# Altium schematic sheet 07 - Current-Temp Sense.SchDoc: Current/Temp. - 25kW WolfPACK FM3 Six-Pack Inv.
size 431 x 279 mm; Date: 09/2024; DocumentNumber: CRD25DA12N-FMC; Revision: 2.0; SheetNumber: 7; SheetTotal: 9; SheetSize: B
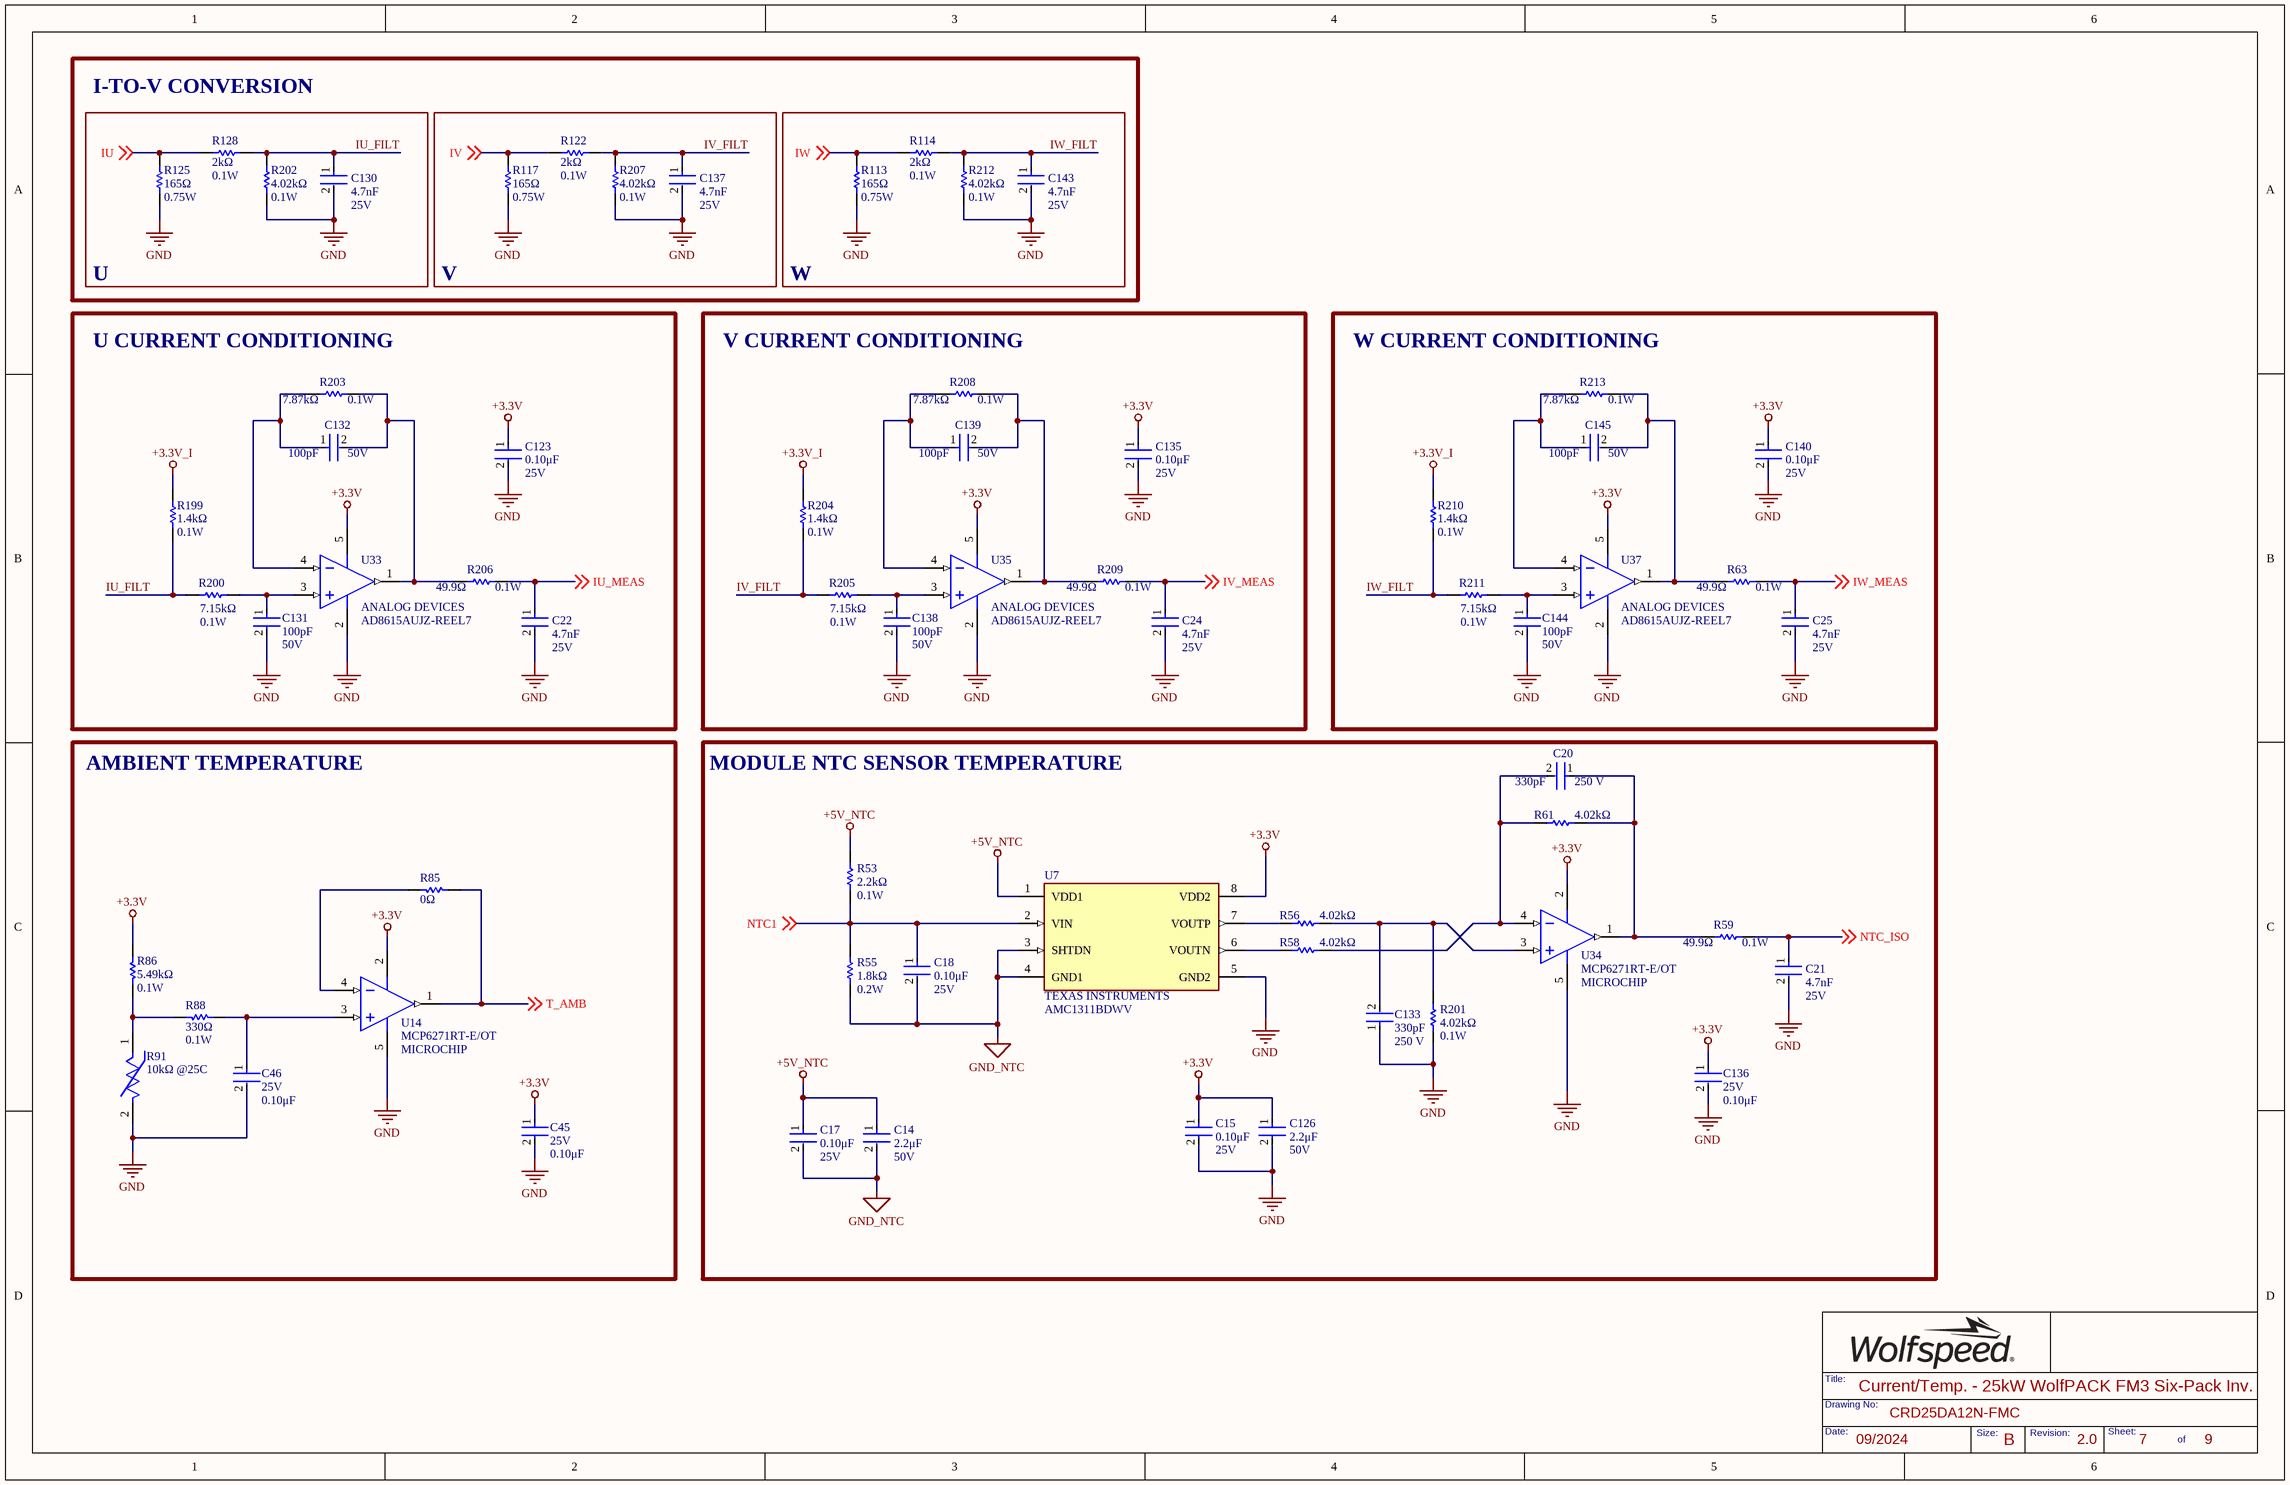
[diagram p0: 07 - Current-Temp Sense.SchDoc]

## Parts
C14  Voltage Rating: 50V  Capacitance: 2.2μF  [FP-C0603C-CF-IPC_B]  (hidden comment: GRT188R61H225ME13D)
C15  Voltage Rating: 25V  Capacitance: 0.10μF  [FP-C0603C-CF-IPC_B]  (hidden comment: C0603C104K3RACTU)
C17  Voltage Rating: 25V  Capacitance: 0.10μF  [FP-C0603C-CF-IPC_B]  (hidden comment: C0603C104K3RACTU)
C18  Voltage Rating: 25V  Capacitance: 0.10μF  [FP-C0603C-CF-IPC_B]  (hidden comment: C0603C104K3RACTU)
C20  value 330pF  Voltage Rating: 250 V  [FP-C0603C-CF-IPC_B]  (hidden comment: C0603C331JAGAC7867)
C21  Voltage Rating: 25V  Capacitance: 4.7nF  [FP-C0603C-CF-IPC_B]  (hidden comment: C0603C472K3RAC7867)
C22  Voltage Rating: 25V  Capacitance: 4.7nF  [FP-C0603C-CF-IPC_B]  (hidden comment: C0603C472K3RAC7867)
C24  Voltage Rating: 25V  Capacitance: 4.7nF  [FP-C0603C-CF-IPC_B]  (hidden comment: C0603C472K3RAC7867)
C25  Voltage Rating: 25V  Capacitance: 4.7nF  [FP-C0603C-CF-IPC_B]  (hidden comment: C0603C472K3RAC7867)
C45  Voltage Rating: 25V  Capacitance: 0.10μF  [FP-C0603C-CF-IPC_B]  (hidden comment: C0603C104K3RACTU)
C46  Voltage Rating: 25V  Capacitance: 0.10μF  [FP-C0603C-CF-IPC_B]  (hidden comment: C0603C104K3RACTU)
C123  Voltage Rating: 25V  Capacitance: 0.10μF  [FP-C0603C-CF-IPC_B]  (hidden comment: C0603C104K3RACTU)
C126  Voltage Rating: 50V  Capacitance: 2.2μF  [FP-C0603C-CF-IPC_B]  (hidden comment: GRT188R61H225ME13D)
C130  Voltage Rating: 25V  Capacitance: 4.7nF  [FP-C0603C-CF-IPC_B]  (hidden comment: C0603C472K3RAC7867)
C131  Capacitance: 100pF  Voltage: 50V  [FP-C0603C-CF-IPC_B]  (hidden comment: CL10C101JB8NNNC)
C132  Capacitance: 100pF  Voltage: 50V  [FP-C0603C-CF-IPC_B]  (hidden comment: CL10C101JB8NNNC)
C133  value 330pF  Voltage Rating: 250 V  [FP-C0603C-CF-IPC_B]  (hidden comment: C0603C331JAGAC7867)
C135  Voltage Rating: 25V  Capacitance: 0.10μF  [FP-C0603C-CF-IPC_B]  (hidden comment: C0603C104K3RACTU)
C136  Voltage Rating: 25V  Capacitance: 0.10μF  [FP-C0603C-CF-IPC_B]  (hidden comment: C0603C104K3RACTU)
C137  Voltage Rating: 25V  Capacitance: 4.7nF  [FP-C0603C-CF-IPC_B]  (hidden comment: C0603C472K3RAC7867)
C138  Capacitance: 100pF  Voltage: 50V  [FP-C0603C-CF-IPC_B]  (hidden comment: CL10C101JB8NNNC)
C139  Capacitance: 100pF  Voltage: 50V  [FP-C0603C-CF-IPC_B]  (hidden comment: CL10C101JB8NNNC)
C140  Voltage Rating: 25V  Capacitance: 0.10μF  [FP-C0603C-CF-IPC_B]  (hidden comment: C0603C104K3RACTU)
C143  Voltage Rating: 25V  Capacitance: 4.7nF  [FP-C0603C-CF-IPC_B]  (hidden comment: C0603C472K3RAC7867)
C144  Capacitance: 100pF  Voltage: 50V  [FP-C0603C-CF-IPC_B]  (hidden comment: CL10C101JB8NNNC)
C145  Capacitance: 100pF  Voltage: 50V  [FP-C0603C-CF-IPC_B]  (hidden comment: CL10C101JB8NNNC)
R53  value 2.2kΩ  Power: 0.1W  [FP-MCR03-IPC_B]  (hidden comment: RC0603FR-072K2L)
R55  Resistance: 1.8kΩ  Max Power Dissipation: 0.2W  [FP-MCR03-IPC_B]  (hidden comment: ERJ-PB3B1801V)
R56  Resistance: 4.02kΩ  [FP-MCR03-IPC_B]  (hidden comment: ERA3AEB4021V)
R58  Resistance: 4.02kΩ  [FP-MCR03-IPC_B]  (hidden comment: ERA3AEB4021V)
R59  Resistance: 49.9Ω  Power Rating: 0.1W  [FP-MCR03-IPC_B]  (hidden comment: ERJ-3EKF49R9V)
R61  Resistance: 4.02kΩ  [FP-MCR03-IPC_B]  (hidden comment: ERA3AEB4021V)
R63  Resistance: 49.9Ω  Power Rating: 0.1W  [FP-MCR03-IPC_B]  (hidden comment: ERJ-3EKF49R9V)
R85  Resistance: 0Ω  [FP-MCR03-IPC_B]  (hidden comment: CRCW06030000Z0EB)
R86  value 5.49kΩ  Power Rating: 0.1W  [FP-MCR03-IPC_B]  (hidden comment: RC0603FR-075K49L)
R88  Resistance: 330Ω  Power Rating: 0.1W  [FP-MCR03-IPC_B]  (hidden comment: RC0603FR-13330RL)
R91  value 10kΩ @25C  [FP-NCU18-0_15-IPC_B]  (hidden comment: NCU18XH103F6SRB)
R113  value 165Ω  Power: 0.75W  [FP-CRCW2010-e3-IPC_B]  (hidden comment: CRCW2010165RFKEF)
R114  Resistance: 2kΩ  Power Rating: 0.1W  [FP-MCR03-IPC_B]  (hidden comment: RT0603DRE072KL)
R117  value 165Ω  Power: 0.75W  [FP-CRCW2010-e3-IPC_B]  (hidden comment: CRCW2010165RFKEF)
R122  Resistance: 2kΩ  Power Rating: 0.1W  [FP-MCR03-IPC_B]  (hidden comment: RT0603DRE072KL)
R125  value 165Ω  Power: 0.75W  [FP-CRCW2010-e3-IPC_B]  (hidden comment: CRCW2010165RFKEF)
R128  Resistance: 2kΩ  Power Rating: 0.1W  [FP-MCR03-IPC_B]  (hidden comment: RT0603DRE072KL)
R199  value 1.4kΩ  Power: 0.1W  [FP-MCR03-IPC_B]  (hidden comment: RT0603DRD071K4L)
R200  Resistance: 7.15kΩ  Power Rating: 0.1W  [FP-MCR03-IPC_B]  (hidden comment: RMCF0603FT7K15)
R201  Power: 0.1W  Resistance: 4.02kΩ  [FP-MCR03-IPC_B]  (hidden comment: ERA3AEB4021V)
R202  Resistance: 4.02kΩ  Power Rating: 0.1W  [FP-MCR03-IPC_B]  (hidden comment: ERA3AEB4021V)
R203  Resistance: 7.87kΩ  Max Power Dissipation: 0.1W  [FP-MCR03-IPC_B]  (hidden comment: RC0603FR-077K87L)
R204  value 1.4kΩ  Power: 0.1W  [FP-MCR03-IPC_B]  (hidden comment: RT0603DRD071K4L)
R205  Resistance: 7.15kΩ  Power Rating: 0.1W  [FP-MCR03-IPC_B]  (hidden comment: RMCF0603FT7K15)
R206  Resistance: 49.9Ω  Power Rating: 0.1W  [FP-MCR03-IPC_B]  (hidden comment: ERJ-3EKF49R9V)
R207  Resistance: 4.02kΩ  Power Rating: 0.1W  [FP-MCR03-IPC_B]  (hidden comment: ERA3AEB4021V)
R208  Resistance: 7.87kΩ  Max Power Dissipation: 0.1W  [FP-MCR03-IPC_B]  (hidden comment: RC0603FR-077K87L)
R209  Resistance: 49.9Ω  Power Rating: 0.1W  [FP-MCR03-IPC_B]  (hidden comment: ERJ-3EKF49R9V)
R210  value 1.4kΩ  Power: 0.1W  [FP-MCR03-IPC_B]  (hidden comment: RT0603DRD071K4L)
R211  Resistance: 7.15kΩ  Power Rating: 0.1W  [FP-MCR03-IPC_B]  (hidden comment: RMCF0603FT7K15)
R212  Resistance: 4.02kΩ  Power Rating: 0.1W  [FP-MCR03-IPC_B]  (hidden comment: ERA3AEB4021V)
R213  Resistance: 7.87kΩ  Max Power Dissipation: 0.1W  [FP-MCR03-IPC_B]  (hidden comment: RC0603FR-077K87L)
U7  AMC1311BDWV  Manufacturer: TEXAS INSTRUMENTS  [FP-DWV0008A-MFG]
U14  Manufacturer: MICROCHIP  [ADI-UJ-5_M]  (hidden comment: MCP6271RT-E/OT)
U33  Manufacturer: ANALOG DEVICES  [ADI-UJ-5_M]  (hidden comment: AD8615AUJZ-REEL7)
U34  Manufacturer: MICROCHIP  [ADI-UJ-5_M]  (hidden comment: MCP6271RT-E/OT)
U35  Manufacturer: ANALOG DEVICES  [ADI-UJ-5_M]  (hidden comment: AD8615AUJZ-REEL7)
U37  Manufacturer: ANALOG DEVICES  [ADI-UJ-5_M]  (hidden comment: AD8615AUJZ-REEL7)

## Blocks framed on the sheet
V: C137 R117 R122 R207
W: C143 R113 R114 R212
U CURRENT CONDITIONING: C22 C123 C131 C132 R199 R200 R203 R206 U33
V CURRENT CONDITIONING: C24 C135 C138 C139 R204 R205 R208 R209 U35
W CURRENT CONDITIONING: C25 C140 C144 C145 R63 R210 R211 R213 U37
AMBIENT TEMPERATURE: C45 C46 R85 R86 R88 R91 U14
MODULE NTC SENSOR TEMPERATURE: C14 C15 C17 C18 C20 C21 C126 C133 C136 R53 R55 R56 R58 R59 R61 R201 U7 U34

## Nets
+3.3V: C15.1 C45.1 C123.1 C126.1 C135.1 C136.1 C140.1 R86.2 U7.8(VDD2) U14.2(+V) U33.5(+V) U34.2(+V) U35.5(+V) U37.5(+V)
+3.3V_I: R199.2 R204.2 R210.2
+5V_NTC: C14.1 C17.1 R53.2 U7.1(VDD1)
GND: C15.2 C21.2 C22.2 C24.2 C25.2 C45.2 C46.2 C123.2 C126.2 C130.2 C131.2 C133.1 C135.2 C136.2 C137.2 C138.2 C140.2 C143.2 C144.2 R91.2 R113.1 R117.1 R125.1 R201.2 R202.1 R207.1 R212.1 U7.5(GND2) U14.5(-V) U33.2(-V) U34.5(-V) U35.2(-V) U37.2(-V)
GND_NTC: C14.2 C17.2 C18.2 R55.1 U7.3(SHTDN) U7.4(GND1)
IU: R125.2 R128.1 ; off-sheet IU
IU_FILT: C130.1 R128.2 R199.1 R200.1 R202.2
IU_MEAS: C22.1 R206.2 ; off-sheet IU_MEAS
IV: R117.2 R122.1 ; off-sheet IV
IV_FILT: C137.1 R122.2 R204.1 R205.1 R207.2
IV_MEAS: C24.1 R209.2 ; off-sheet IV_MEAS
IW: R113.2 R114.1 ; off-sheet IW
IW_FILT: C143.1 R114.2 R210.1 R211.1 R212.2
IW_MEAS: C25.1 R63.2 ; off-sheet IW_MEAS
NTC1: C18.1 R53.1 R55.2 U7.2(VIN) ; off-sheet NTC1
NTC_ISO: C21.1 R59.2 ; off-sheet NTC_ISO
T_AMB: R85.1 U14.1(OUT) ; off-sheet T_AMB
NetC20_1: C20.1 R59.1 R61.1 U34.1(OUT)
NetC20_2: C20.2 R58.1 R61.2 U34.4(-IN)
NetC46_1: C46.1 R88.2 U14.3(+IN)
NetC131_1: C131.1 R200.2 U33.3(+IN)
NetC132_1: C132.1 R203.1 U33.4(-IN)
NetC132_2: C132.2 R203.2 R206.1 U33.1(OUT)
NetC133_2: C133.2 R56.1 R201.1 U34.3(+IN)
NetC138_1: C138.1 R205.2 U35.3(+IN)
NetC139_1: C139.1 R208.1 U35.4(-IN)
NetC139_2: C139.2 R208.2 R209.1 U35.1(OUT)
NetC144_1: C144.1 R211.2 U37.3(+IN)
NetC145_1: C145.1 R213.1 U37.4(-IN)
NetC145_2: C145.2 R63.1 R213.2 U37.1(OUT)
NetR56_2: R56.2 U7.7(VOUTP)
NetR58_2: R58.2 U7.6(VOUTN)
NetR85_2: R85.2 U14.4(-IN)
NetR86_1: R86.1 R88.1 R91.1

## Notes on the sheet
- I-TO-V CONVERSION
- U

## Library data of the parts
C14 C126 = GRT188R61H225ME13D: CAP CER 2.2UF 50V X5R 0603; Manufacturer: MURATA; Tolerance: 20%; Value: 2.2μF
C15 C17 C18 C45 C46 C123 C135 C136 C140 = CMP-2006-03057-2: CAP CER 0.1UF 25V X7R 0603; Manufacturer: KEMET; Value: 0.10μF; Material: Ceramic; Tolerance: 0.1; Temperature Coefficient: 30ppm/°C; Automotive Grade: Grade 1
C20 C133 = CMP-03020-020944-2: CAP CER 330PF 250V C0G/NP0 0603; Manufacturer: KEMET; Material: Ceramic; Temperature Coefficient: 30ppm/°C; Tolerance: 0.05; Automotive Grade: Grade 1; Temperature Characteristic: C0G
C21 C22 C24 C25 C130 C137 C143 = C0603C472K3RAC7867: CAP CER 4700PF 25V 10% X7R 0603; Manufacturer: KEMET; Manufacturer Part Number: C0603C472K3RACTU; Dielectric Material: Ceramic; Value: 4.7nF
C131 C132 C138 C139 C144 C145 = CL10C101JB8NNNC: CAP CER 100PF 50V C0G/NP0 0603; Manufacturer: SAMSUNG; Material: Ceramic; Tolerance: 5%; Dielectric: C0G; Temperature Coefficient: 300ppm/°C
R53 = RC0603FR-072K2L: RES 2.2K OHM 1% 1/10W 0603; Manufacturer: YAGEO
R55 = ERJ-PB3B1801V: RES SMD 1.8K OHM 0.1% 1/5W 0603; Manufacturer: PANASONIC; Temperature Coefficient: 50ppm/°C; Value: 1.8kΩ
R56 R58 R61 R202 R207 R212 = ERA3AEB4021V: RES SMD 4.02KOHM 0.1% 1/10W 0603; Manufacturer: PANASONIC; Manufacturer Part Number: ERA-3AEB4021V; Voltage Rating: 75V; Temperature Coefficient: 25ppm/°C; Max Power Dissipation: 100mW; Value: 4.02kΩ
R59 R63 R206 R209 = ERJ-3EKF49R9V: RES SMD 49.9 OHM 1% 1/10W 0603; Manufacturer: PANASONIC; Temperature Coefficient: 100ppm/°C; Voltage Rating: 75V; Max Power Dissipation: 100mW; Voltage Rating (DC): 50V; Working Voltage: 6V; Value: 49.9Ω
R85 = CRCW06030000Z0EB: RES SMD 0 OHM JUMPER 1/10W 0603; Manufacturer: VISHAY DALE; Manufacturer Part Number: CRCW06030000Z0EBC; Max Power Dissipation: 100mW; Voltage Rating: 75V; Tolerance: 1%; Temperature Coefficient: 100ppm/°C; Value: 0Ω
R86 = RC0603FR-075K49L: RES 5.49K OHM 1% 1/10W 0603; Manufacturer: YAGEO; Temperature Coefficient: 100ppm/°C; Voltage Rating: 50V; Max Power Dissipation: 100mW
R88 = RC0603FR-13330RL: RES 330 OHM 1% 1/10W 0603; Manufacturer: YAGEO; Voltage Rating: 50V; Temperature Coefficient: 100ppm/°C; Value: 330Ω
R91 = CMP-06022-000547-2: THERMISTOR NTC 10KOHM 3380K 0603; Manufacturer: MURATA
R113 R117 R125 = CRCW2010165RFKEF: RES SMD 165 OHM 1% 3/4W 2010; Manufacturer: VISHAY
R114 R122 R128 = RT0603DRE072KL: RES SMD 2K OHM 0.5% 1/10W 0603; Manufacturer: YAGEO; Temperature Coefficient: 50ppm/°C; Voltage Rating: 75V; Max Power Dissipation: 100mW; Voltage Rating (DC): 50V; Value: 2kΩ
R199 R204 R210 = RT0603DRD071K4L: RES SMD 1.4K OHM 0.5% 1/10W 0603; Manufacturer: YAGEO
R200 R205 R211 = RMCF0603FT7K15: RES 7.15K OHM 1% 1/10W 0603; Manufacturer: STACKPOLE; Max Power Dissipation: 100mW; Temperature Coefficient: 100ppm/°C; Value: 7.15kΩ
R201 = ERA3AEB4021V: RES SMD 4.02KOHM 0.1% 1/10W 0603; Manufacturer: PANASONIC; Manufacturer Part Number: ERA-3AEB4021V; Voltage Rating: 75V; Temperature Coefficient: 25ppm/°C; Value: 4.02kΩ
R203 R208 R213 = RC0603FR-077K87L: RES 7.87K OHM 1% 1/10W 0603; Manufacturer: YAGEO; Power Rating: 100mW; Temperature Coefficient: 100ppm/°C; Voltage Rating: 50V; Value: 7.87kΩ
U7 = CMP-04893-000001-1: IC ISOLATION 8SOIC; Input Offset Voltage: -1.1mV; Standoff Height: 0.36mm; Max Junction Temp: +150°C; Number Of Channels: 1; Input Bias Current: 0.0035uA; Max Supply Voltage: 5.5V; Min Supply Voltage: 3V; Nominal Supply Current: 1.3-7100uA
U14 U34 = MCP6271RT-E/OT: IC OPAMP GP 1 CIRCUIT SOT23-5
U33 U35 U37 = CMP-0384-02059-2: IC OPAMP GP 1 CIRCUIT TSOT23-5; Generic Part Number: AD8615; Iq/Amp: 1.7mA; V Span Max: 6V; Amplifiers Per Package: 1; Small Signal Bandwidth: 23MHz; Input Offset Voltage: 80uV; V Span Min: 2.7V; Slew Rate: 12V/us; Input Bias Current: 200fA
